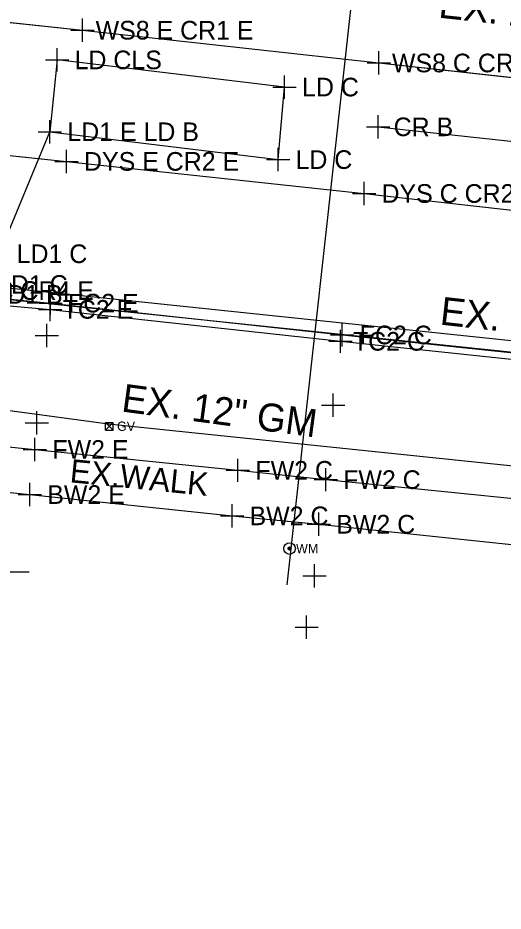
# Model space of a CAD drawing. Extents: x 1363693 to 1365209, y 422201 to 424153.
# Drawn here: x 1364314 to 1364355.7, y 423032 to 423108.7 of the extents above; entities that cross this region are included whole.
import ezdxf

# ---------------------------------------------------------------- set-up
doc = ezdxf.new("R2010")
doc.units = 0
for name, color, linetype in [('BASELINE-CL-RW', 7, 'Continuous'), ('DR_X_Storm_Sewer', 7, 'Continuous'), ('DR_X_Text', 7, 'Continuous'), ('O-ALGN-BASELINE-WERK-CL-RW', 7, 'Continuous'), ('O-ALGN-TEXT-BASELINE-WERK-CL-RW', 7, 'Continuous'), ('OWNERS', 7, 'Continuous'), ('PM_X_Channelizing_Line', 7, 'Continuous'), ('PM_X_CL_Double_Solid', 7, 'Continuous'), ('RD_X_Text', 7, 'Continuous'), ('SG_X_Wiring', 7, 'Continuous'), ('SV_X_Original_Ground', 7, 'Continuous'), ('SV_X_Shot_Marker', 7, 'Continuous'), ('UT_X_Gas', 7, 'Continuous'), ('UT_X_Gas_Cells', 7, 'Continuous'), ('UT_X_Gas_Text', 7, 'Continuous'), ('UT_X_Water', 7, 'Continuous'), ('UT_X_Water_Text', 7, 'Continuous')]:
    doc.layers.add(name, color=color, linetype=linetype)

msp = doc.modelspace()

# ---------------------------------------------------------------- linework, layer by layer
at = {"layer": 'BASELINE-CL-RW'}
msp.add_lwpolyline([(1364281.261, 423085.858), (1364282.338, 423086.049), (1364282.338, 423086.049), (1364282.675, 423086.092), (1364282.675, 423086.092), (1364283.948, 423086.188), (1364283.948, 423086.188), (1364287.336, 423086.384), (1364287.336, 423086.384), (1364288.949, 423086.397), (1364288.949, 423086.397), (1364291.9, 423086.216), (1364291.9, 423086.216), (1364299.528, 423085.512), (1364302.793, 423085.085), (1364305.795, 423084.692), (1364316.8, 423083.687), (1364341.72, 423080.943), (1364362.907, 423078.726), (1364364.112, 423078.604)], dxfattribs=at)
at = {"layer": 'DR_X_Storm_Sewer'}
for points in [[(1364303.029, 423086.6), (1364405.322, 423075.89), (1364518.74, 423064.501), (1364619.101, 423057.097)], [(1364619.028, 423056.1), (1364518.653, 423063.505), (1364405.22, 423074.896), (1364302.925, 423085.605)]]:
    msp.add_lwpolyline(points, dxfattribs=at)
at = {"layer": 'O-ALGN-BASELINE-WERK-CL-RW'}
for points in [[(1363946.375, 423147.199), (1363971.317, 423144.667), (1363995.58, 423142.128), (1364021.135, 423139.461), (1364045.823, 423136.819), (1364070.743, 423134.279), (1364095.743, 423131.549), (1364120.337, 423128.876), (1364145.279, 423126.289), (1364170.549, 423123.503), (1364184.679, 423122.2), (1364194.698, 423121.631), (1364223.029, 423118.455), (1364241.587, 423116.486), (1364258.097, 423114.418), (1364276.821, 423112.152), (1364285.05, 423111.214), (1364289.541, 423110.849), (1364295.586, 423110.248), (1364319.585, 423107.658), (1364345.02, 423104.847), (1364369.674, 423102.16)], [(1363945.13, 423135.819), (1363969.932, 423133.318), (1363994.815, 423130.662), (1364019.895, 423128.137), (1364044.452, 423125.58), (1364069.276, 423123.015), (1364094.56, 423120.359), (1364119.159, 423117.933), (1364144.273, 423115.157), (1364169.12, 423112.53), (1364192.84, 423110.067), (1364221.831, 423106.718), (1364240.003, 423104.877), (1364257.486, 423102.742), (1364275.788, 423101.018), (1364283.924, 423100.028), (1364293.674, 423098.73), (1364296.797, 423098.651), (1364318.208, 423096.395), (1364343.743, 423093.638), (1364368.133, 423090.887)], [(1364344.949, 423099.36), (1364369.026, 423096.77), (1364393.032, 423094.129), (1364418.879, 423091.081), (1364442.643, 423088.825), (1364467.917, 423086.086), (1364493.18, 423083.679), (1364518.018, 423081.408), (1364543.181, 423079.173), (1364568.054, 423076.965), (1364592.54, 423074.839), (1364617.51, 423072.5), (1364642.473, 423070.404), (1364666.864, 423068.234), (1364691.478, 423065.715)]]:
    msp.add_lwpolyline(points, dxfattribs=at)
at = {"layer": 'O-ALGN-TEXT-BASELINE-WERK-CL-RW'}
for points in [[(1364282.675, 423086.092), (1364283.409, 423082.946), (1364285.461, 423074.768), (1364290.512, 423074.176), (1364315.49, 423071.656), (1364332.921, 423069.866), (1364340.452, 423069.065), (1364368.178, 423066.273)], [(1364273.238, 423032.012), (1364275.575, 423045.365), (1364277.753, 423058.717), (1364279.662, 423071.459), (1364290.031, 423070.331), (1364315.055, 423067.784), (1364332.416, 423065.954), (1364339.859, 423065.236), (1364367.783, 423062.301)]]:
    msp.add_lwpolyline(points, dxfattribs=at)
at = {"layer": 'OWNERS'}
msp.add_lwpolyline([(1364272.57, 423083.839), (1364277.514, 423085.565), (1364277.514, 423085.565), (1364281.174, 423086.365), (1364287.374, 423086.871), (1364287.374, 423086.871), (1364292.044, 423086.773), (1364292.044, 423086.773), (1364299.541, 423086.059), (1364305.976, 423085.301), (1364316.835, 423084.22), (1364341.877, 423081.489), (1364364.186, 423079.145)], dxfattribs=at)
at = {"layer": 'PM_X_Channelizing_Line'}
for p, q in [((1364295.586, 423110.248), (1364319.585, 423107.658)), ((1364295.586, 423110.248), (1364319.585, 423107.658)), ((1364319.585, 423107.658), (1364345.02, 423104.847)), ((1364319.585, 423107.658), (1364345.02, 423104.847)), ((1364345.02, 423104.847), (1364369.674, 423102.16)), ((1364345.02, 423104.847), (1364369.674, 423102.16)), ((1364296.797, 423098.651), (1364318.208, 423096.395)), ((1364318.208, 423096.395), (1364343.743, 423093.638)), ((1364343.743, 423093.638), (1364368.133, 423090.887))]:
    msp.add_line(p, q, dxfattribs=at)
at = {"layer": 'PM_X_CL_Double_Solid'}
for p, q in [((1364296.797, 423098.651), (1364318.208, 423096.395)), ((1364318.208, 423096.395), (1364343.743, 423093.638)), ((1364343.743, 423093.638), (1364368.133, 423090.887))]:
    msp.add_line(p, q, dxfattribs=at)
at = {"layer": 'SG_X_Wiring'}
for p, q in [((1364317.398, 423105.109), (1364316.775, 423098.937)), ((1364336.925, 423102.778), (1364317.398, 423105.109)), ((1364336.364, 423096.548), (1364336.925, 423102.778)), ((1364312.424, 423088.464), (1364316.775, 423098.937)), ((1364316.775, 423098.937), (1364336.364, 423096.548))]:
    msp.add_line(p, q, dxfattribs=at)
at = {"layer": 'SV_X_Original_Ground'}
for p, q in [((1364319.585, 423106.658), (1364319.585, 423108.658)), ((1364318.585, 423107.658), (1364320.585, 423107.658)), ((1364345.02, 423103.847), (1364345.02, 423105.847)), ((1364344.02, 423104.847), (1364346.02, 423104.847)), ((1364344.949, 423098.36), (1364344.949, 423100.36)), ((1364316.775, 423097.937), (1364316.775, 423099.937)), ((1364315.775, 423098.937), (1364317.775, 423098.937)), ((1364343.949, 423099.36), (1364345.949, 423099.36)), ((1364318.208, 423095.395), (1364318.208, 423097.395)), ((1364317.208, 423096.395), (1364319.208, 423096.395)), ((1364343.743, 423092.638), (1364343.743, 423094.638)), ((1364342.743, 423093.638), (1364344.743, 423093.638)), ((1364316.514, 423080.452), (1364316.514, 423082.452)), ((1364315.514, 423081.452), (1364317.514, 423081.452)), ((1364341.093, 423074.463), (1364341.093, 423076.463)), ((1364315.65, 423072.944), (1364315.65, 423074.944)), ((1364340.093, 423075.463), (1364342.093, 423075.463)), ((1364314.65, 423073.944), (1364316.65, 423073.944)), ((1364339.501, 423059.808), (1364339.501, 423061.808)), ((1364312.992, 423061.135), (1364314.992, 423061.135)), ((1364338.501, 423060.808), (1364340.501, 423060.808)), ((1364338.819, 423055.392), (1364338.819, 423057.392)), ((1364337.819, 423056.392), (1364339.819, 423056.392))]:
    msp.add_line(p, q, dxfattribs=at)
at = {"layer": 'SV_X_Shot_Marker'}
for p, q in [((1364317.398, 423104.109), (1364317.398, 423106.109)), ((1364316.398, 423105.109), (1364318.398, 423105.109)), ((1364336.925, 423101.778), (1364336.925, 423103.778)), ((1364335.925, 423102.778), (1364337.925, 423102.778)), ((1364336.364, 423095.548), (1364336.364, 423097.548)), ((1364335.364, 423096.548), (1364337.364, 423096.548)), ((1364316.835, 423083.22), (1364316.835, 423085.22)), ((1364315.835, 423084.22), (1364317.835, 423084.22)), ((1364316.8, 423082.687), (1364316.8, 423084.687)), ((1364315.8, 423083.687), (1364317.8, 423083.687)), ((1364341.72, 423079.943), (1364341.72, 423081.943)), ((1364341.877, 423080.489), (1364341.877, 423082.489)), ((1364340.877, 423081.489), (1364342.877, 423081.489)), ((1364340.72, 423080.943), (1364342.72, 423080.943)), ((1364315.49, 423070.656), (1364315.49, 423072.656)), ((1364314.49, 423071.656), (1364316.49, 423071.656)), ((1364332.921, 423068.866), (1364332.921, 423070.866)), ((1364331.921, 423069.866), (1364333.921, 423069.866)), ((1364340.452, 423068.065), (1364340.452, 423070.065)), ((1364315.055, 423066.784), (1364315.055, 423068.784)), ((1364339.452, 423069.065), (1364341.452, 423069.065)), ((1364314.055, 423067.784), (1364316.055, 423067.784)), ((1364332.416, 423064.954), (1364332.416, 423066.954)), ((1364331.416, 423065.954), (1364333.416, 423065.954)), ((1364339.859, 423064.236), (1364339.859, 423066.236)), ((1364338.859, 423065.236), (1364340.859, 423065.236))]:
    msp.add_line(p, q, dxfattribs=at)
at = {"layer": 'UT_X_Gas'}
msp.add_lwpolyline([(1363697.823, 423150.328), (1364024.78, 423111.733), (1364079.651, 423106.56), (1364321.815, 423073.856), (1364574.009, 423047.674), (1364582.932, 423046.282), (1364615.757, 423042.884), (1364684.796, 423035.164)], dxfattribs=at)
at = {"layer": 'UT_X_Gas_Cells'}
for p, q in [((1364321.544, 423073.319), (1364322.209, 423073.984)), ((1364321.544, 423073.984), (1364322.209, 423073.319)), ((1364321.544, 423073.984), (1364322.209, 423073.984)), ((1364321.544, 423073.319), (1364321.544, 423073.984)), ((1364321.544, 423073.319), (1364322.209, 423073.319)), ((1364322.209, 423073.319), (1364322.209, 423073.984))]:
    msp.add_line(p, q, dxfattribs=at)
at = {"layer": 'UT_X_Water'}
msp.add_line((1364337.158, 423060.037), (1364343.707, 423119.398), dxfattribs=at)
for points in [[(1364337.237, 423063.217), (1364337.352, 423063.15), (1364337.352, 423063.15), (1364337.219, 423063.15)], [(1364337.219, 423063.15), (1364337.352, 423063.15), (1364337.352, 423063.15), (1364337.237, 423063.083)], [(1364337.285, 423063.265), (1364337.352, 423063.15), (1364337.352, 423063.15), (1364337.237, 423063.217)], [(1364337.237, 423063.083), (1364337.352, 423063.15), (1364337.352, 423063.15), (1364337.285, 423063.035)], [(1364337.352, 423063.283), (1364337.352, 423063.15), (1364337.352, 423063.15), (1364337.285, 423063.265)], [(1364337.285, 423063.035), (1364337.352, 423063.15), (1364337.352, 423063.15), (1364337.352, 423063.017)], [(1364337.419, 423063.265), (1364337.352, 423063.15), (1364337.352, 423063.15), (1364337.352, 423063.283)], [(1364337.467, 423063.217), (1364337.352, 423063.15), (1364337.352, 423063.15), (1364337.419, 423063.265)], [(1364337.485, 423063.15), (1364337.352, 423063.15), (1364337.352, 423063.15), (1364337.467, 423063.217)], [(1364337.352, 423063.017), (1364337.352, 423063.15), (1364337.352, 423063.15), (1364337.419, 423063.035)], [(1364337.419, 423063.035), (1364337.352, 423063.15), (1364337.352, 423063.15), (1364337.467, 423063.083)], [(1364337.467, 423063.083), (1364337.352, 423063.15), (1364337.352, 423063.15), (1364337.485, 423063.15)]]:
    msp.add_lwpolyline(points, close=True, dxfattribs=at)
msp.add_circle((1364337.352, 423063.15), 0.5, dxfattribs=at)

# ---------------------------------------------------------------- texts
at = {"layer": 'DR_X_Text'}
msp.add_text('EX. 15" STM.', height=2.4, rotation=353.66359, dxfattribs=at).set_placement((1364350.197, 423082.388))
at = {"layer": 'RD_X_Text'}
msp.add_text('EX.WALK', height=2, rotation=354.30306, dxfattribs=at).set_placement((1364318.434, 423068.847))
at = {"layer": 'SV_X_Original_Ground'}
for s, p in [('WS8 E CR1 E', (1364320.704, 423106.858)), ('WS8 C CR1 C', (1364346.139, 423104.047)), ('CR B', (1364346.286, 423098.56)), ('LD1 E LD B', (1364318.275, 423098.137)), ('DYS E CR2 E', (1364319.708, 423095.595)), ('DYS C CR2 C', (1364345.243, 423092.838)), ('LD1 C', (1364313.924, 423087.664)), ('LD1 C', (1364312.241, 423085.022)), ('LD1 B', (1364311.926, 423084.18))]:
    msp.add_text(s, height=1.6, dxfattribs=at).set_placement(p)
at = {"layer": 'SV_X_Shot_Marker'}
for s, p in [('LD CLS', (1364318.898, 423104.309)), ('LD C', (1364338.425, 423101.978)), ('LD C', (1364337.864, 423095.748)), ('FC2 C CR4 E', (1364307.476, 423084.501)), ('FC2 E', (1364318.335, 423083.42)), ('TC2 E', (1364317.871, 423082.887)), ('TC2 C', (1364342.791, 423080.143)), ('FC2 C', (1364343.377, 423080.689)), ('FW2 E', (1364316.99, 423070.856)), ('FW2 C', (1364334.421, 423069.066)), ('FW2 C', (1364341.952, 423068.265)), ('BW2 E', (1364316.555, 423066.984)), ('BW2 C', (1364333.916, 423065.154)), ('BW2 C', (1364341.359, 423064.436))]:
    msp.add_text(s, height=1.6, dxfattribs=at).set_placement(p)
at = {"layer": 'UT_X_Gas_Text'}
msp.add_text('EX. 12" GM', height=2.4, rotation=352.34452, dxfattribs=at).set_placement((1364322.85, 423074.928))
msp.add_text('GV', height=0.8, dxfattribs=at).set_placement((1364322.545, 423073.252))
at = {"layer": 'UT_X_Water_Text'}
msp.add_text('EX. 24" WM', height=2.4, rotation=353.80061, dxfattribs=at).set_placement((1364350.077, 423108.744))
msp.add_text('WM', height=0.8, dxfattribs=at).set_placement((1364337.912, 423062.75))

doc.saveas('drawing.dxf')
